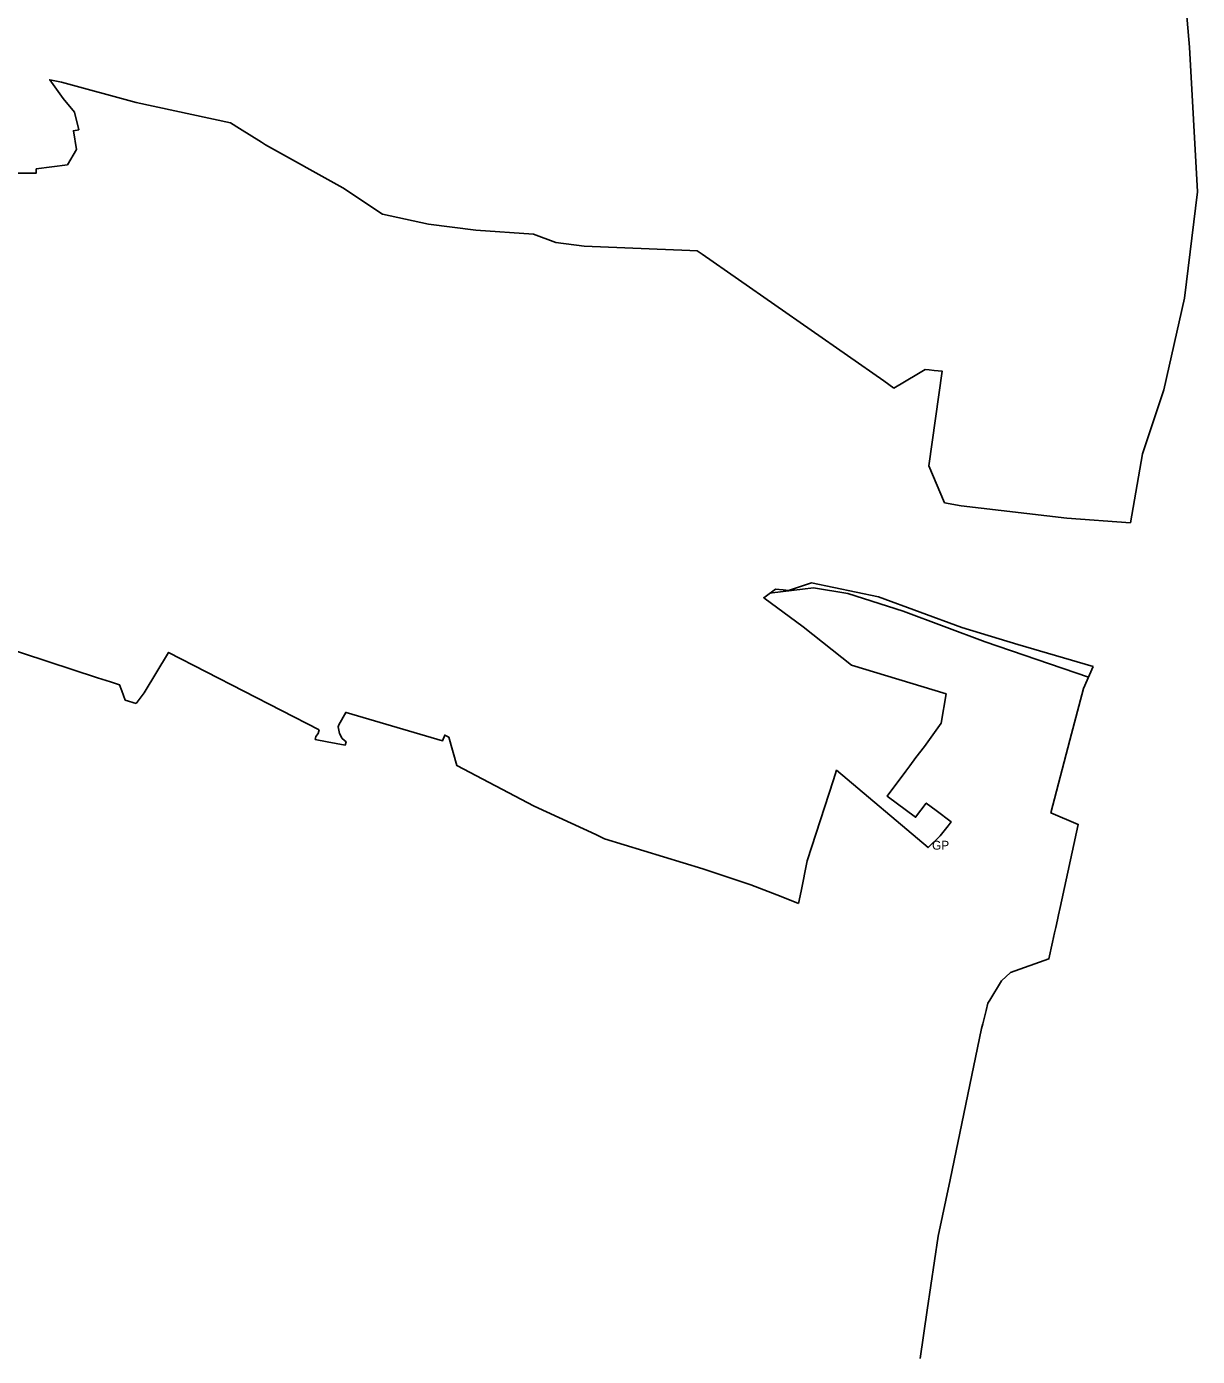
# Model space of a CAD drawing. Extents: x -587103 to -585114, y -1103460 to -1100918.
# Drawn here: x -585642 to -585114, y -1102590 to -1101990 of the extents above; entities that cross this region are included whole.
import ezdxf

# ---------------------------------------------------------------- set-up
doc = ezdxf.new("R2010")
doc.units = 0
for name, color, linetype in [('OVNE_SET', 7, 'Continuous'), ('OVNI_POP', 7, 'Continuous'), ('OVNI_PRE', 7, 'Continuous'), ('OVNI_SET', 7, 'Continuous'), ('VODA', 7, 'Continuous')]:
    doc.layers.add(name, color=color, linetype=linetype)

msp = doc.modelspace()

# ---------------------------------------------------------------- linework, layer by layer
at = {"layer": 'OVNE_SET'}
for points in [[(-585144.69, -1102214.27), (-585139.31, -1102183.16), (-585129.7, -1102154.2), (-585120.28, -1102112.89), (-585114.5, -1102064.88), (-585118.06, -1101999.59), (-585121.16, -1101962.91), (-585126.77, -1101938.28), (-585130.63, -1101929.71)], [(-585239.5, -1102591.28), (-585236.36, -1102569.44), (-585231.36, -1102536.1), (-585226.05, -1102510.62), (-585211.84, -1102442.37), (-585211.3, -1102440.21), (-585209.82, -1102434.31), (-585208.98, -1102430.94), (-585208.13, -1102429.56), (-585202.84, -1102420.94), (-585198.82, -1102417.06), (-585181.42, -1102410.95), (-585179.79, -1102403.45), (-585178.87, -1102399.23), (-585178.34, -1102396.81), (-585177.6, -1102393.41), (-585177.11, -1102391.16), (-585176.38, -1102387.78), (-585168.24, -1102350.31), (-585180.55, -1102345.12), (-585171.98, -1102312.3), (-585165.9, -1102289), (-585161.48, -1102279.03)]]:
    msp.add_lwpolyline(points, dxfattribs=at)
at = {"layer": 'OVNI_PRE'}
for points in [[(-585235.67, -1102188.47), (-585229.56, -1102145.8), (-585233.17, -1102145.44)], [(-585288.55, -1102241.34), (-585258.33, -1102247.54)], [(-585498.86, -1102314.54), (-585498.38, -1102313.01), (-585500.21, -1102311.52), (-585501.35, -1102309.23), (-585501.96, -1102306.32), (-585501.68, -1102305.33)], [(-585512.35, -1102311.99), (-585506.99, -1102313), (-585498.86, -1102314.54)]]:
    msp.add_lwpolyline(points, dxfattribs=at)
at = {"layer": 'OVNI_SET'}
msp.add_line((-585498.86, -1102314.54), (-585498.86, -1102314.54), dxfattribs=at)
for points in [[(-585626.78, -1102015.44), (-585632.06, -1102014.33), (-585626.01, -1102022.82), (-585620.87, -1102028.97), (-585618.96, -1102036.89)], [(-585391.04, -1102089.34), (-585403.87, -1102087.77), (-585413.84, -1102083.94), (-585439.83, -1102082.1), (-585461.18, -1102079.41), (-585481.97, -1102075), (-585499.94, -1102063), (-585534.69, -1102043.69), (-585536.52, -1102042.54), (-585546.52, -1102036.26), (-585550.51, -1102033.76), (-585593.02, -1102024.62), (-585626.78, -1102015.44)], [(-585618.96, -1102036.89), (-585621.38, -1102037.31), (-585619.99, -1102045.84), (-585624.09, -1102052.65), (-585638.16, -1102054.51), (-585638.17, -1102056.49), (-585646.58, -1102056.46)], [(-585391.04, -1102089.34), (-585343.36, -1102091.31), (-585340.06, -1102091.45), (-585337.79, -1102093.04)], [(-585251.34, -1102153.5), (-585255.89, -1102150.22), (-585337.79, -1102093.04)], [(-585233.17, -1102145.44), (-585235.43, -1102145.21), (-585237.19, -1102145.04), (-585240.99, -1102147.31), (-585251.34, -1102153.5)], [(-585228.53, -1102205.23), (-585235.67, -1102188.47)], [(-585228.53, -1102205.23), (-585221.09, -1102206.49), (-585173.43, -1102212.07), (-585144.69, -1102214.27)], [(-585292.23, -1102261.21), (-585310.02, -1102248.02), (-585304.83, -1102244.09), (-585301.33, -1102244.47)], [(-585301.33, -1102244.47), (-585298.82, -1102244.75), (-585288.55, -1102241.34)], [(-585258.33, -1102247.54), (-585220.67, -1102261.51)], [(-585691.04, -1102276.4), (-585681.53, -1102266.04), (-585677.84, -1102262.03), (-585610.46, -1102284.12)], [(-585230.44, -1102355.43), (-585226.95, -1102350.89), (-585225.56, -1102349.08), (-585232.24, -1102344.06), (-585236.78, -1102340.66), (-585241.57, -1102347.07), (-585254.4, -1102337.52), (-585246, -1102326.31), (-585244.2, -1102323.91), (-585241.4, -1102320.17), (-585237.62, -1102315.13), (-585230.09, -1102304.62), (-585227.83, -1102291.4), (-585270.44, -1102278.46), (-585292.23, -1102261.21)], [(-585220.67, -1102261.51), (-585195.41, -1102269.18)], [(-585195.41, -1102269.18), (-585161.48, -1102279.03)], [(-585593.1, -1102295.81), (-585589.52, -1102290.89), (-585578.48, -1102272.72), (-585510.47, -1102307.55)], [(-585610.46, -1102284.12), (-585604.69, -1102286.02), (-585600.56, -1102287.37), (-585599.59, -1102289.95), (-585597.97, -1102294.23), (-585593.1, -1102295.81)], [(-585501.68, -1102305.33), (-585498.52, -1102299.79), (-585498.31, -1102299.85), (-585454.9, -1102312.54), (-585453.93, -1102309.96), (-585452.07, -1102310.98), (-585448.47, -1102323.74), (-585413.53, -1102342.13), (-585385.85, -1102354.91), (-585381.8, -1102356.76)], [(-585510.47, -1102307.55), (-585511.07, -1102309.27), (-585512, -1102310.67), (-585512.35, -1102311.99)], [(-585294.39, -1102385.99), (-585293.24, -1102380.4), (-585290.42, -1102366.65), (-585278.63, -1102330.2), (-585277.21, -1102325.84), (-585235.95, -1102360.71), (-585230.44, -1102355.43)], [(-585381.8, -1102356.76), (-585337.57, -1102370.39), (-585315.83, -1102377.49), (-585302.21, -1102382.89), (-585294.39, -1102385.99)]]:
    msp.add_lwpolyline(points, dxfattribs=at)
at = {"layer": 'VODA'}
msp.add_lwpolyline([(-585163.68, -1102283.82), (-585210.27, -1102267.93), (-585247.24, -1102254.02), (-585272.1, -1102246.07), (-585287.69, -1102243.59), (-585307.42, -1102245.91)], dxfattribs=at)

# ---------------------------------------------------------------- texts
at = {"layer": 'OVNI_POP'}
msp.add_text('GP', height=4, dxfattribs=at).set_placement((-585234.16, -1102361.68))

doc.saveas('drawing.dxf')
